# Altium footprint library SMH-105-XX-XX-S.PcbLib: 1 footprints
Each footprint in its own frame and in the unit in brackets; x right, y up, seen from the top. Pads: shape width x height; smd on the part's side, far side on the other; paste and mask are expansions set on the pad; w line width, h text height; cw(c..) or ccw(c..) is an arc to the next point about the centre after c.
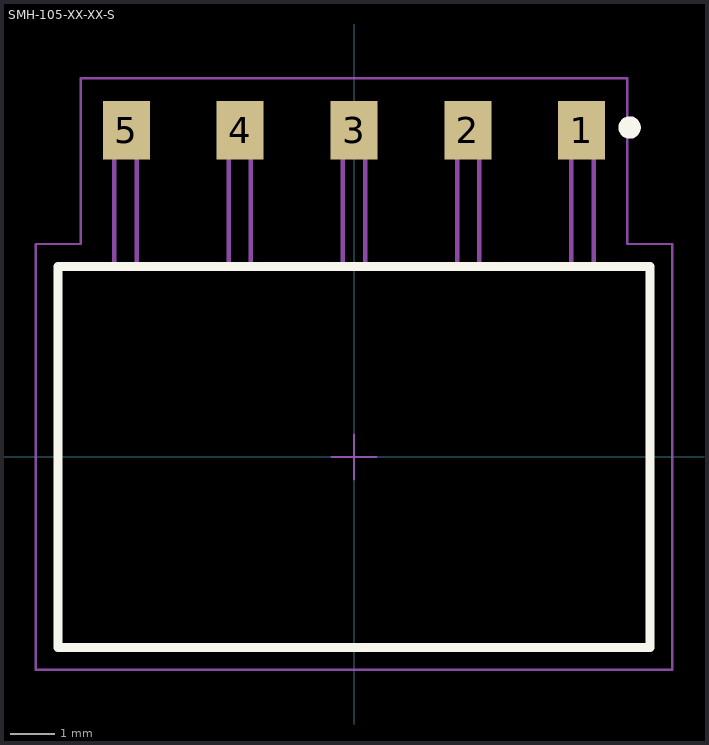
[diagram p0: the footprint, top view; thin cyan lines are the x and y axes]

## SMH-105-XX-XX-S [mm] "2.54mm pitch, socket assembly; horizontal, single row, SMT"
height 4.95
pads (5):
  rect 1.05x1.3 smd mask+0: 1(5.08,7.29) 2(2.54,7.29) 3(0,7.29) 4(-2.54,7.29) 5(-5.08,7.29)
Top Overlay:
  circle w0.25: c6.15,7.35 r0.125
  lines w0.2: -6.6,-4.25 6.6,-4.25 6.6,4.25 -6.6,4.25 -6.6,-4.25
Mechanical 12:
  lines w0.001: -6.6,-4.25 6.6,-4.25 6.6,4.25 -6.6,4.25 -6.6,-4.25
Mechanical 13:
  lines w0.1: -5.35,4.25 -5.35,7.62 -4.85,7.62 -4.85,4.25 ; -2.8,4.25 -2.8,7.62 -2.3,7.62 -2.3,4.25 ; -0.25,4.25 -0.25,7.62 0.25,7.62 0.25,4.25 ; 2.3,4.25 2.3,7.62 2.8,7.62 2.8,4.25 ; 4.85,4.25 4.85,7.62 5.35,7.62 5.35,4.25 ; -6.6,-4.25 6.6,-4.25 6.6,4.25 -6.6,4.25 -6.6,-4.25
  text ".Designator" at 0,-0.127 h1.52
Mechanical 15:
  lines w0.05: -0.5,0 0.5,0 ; 0,-0.5 0,0.5 ; -7.1,-4.75 7.1,-4.75 7.1,4.75 6.1,4.75 6.1,8.45 -6.1,8.45 -6.1,4.75 -7.1,4.75 -7.1,-4.75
